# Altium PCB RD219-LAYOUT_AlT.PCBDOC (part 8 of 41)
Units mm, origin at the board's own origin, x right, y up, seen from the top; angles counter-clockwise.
Board outline 209.75 x 159.97 mm, 2 copper layers (TOP, BOTTOM), stack 0 mm thick; 398 components, 199 nets, 1469 pads, 0 vias.
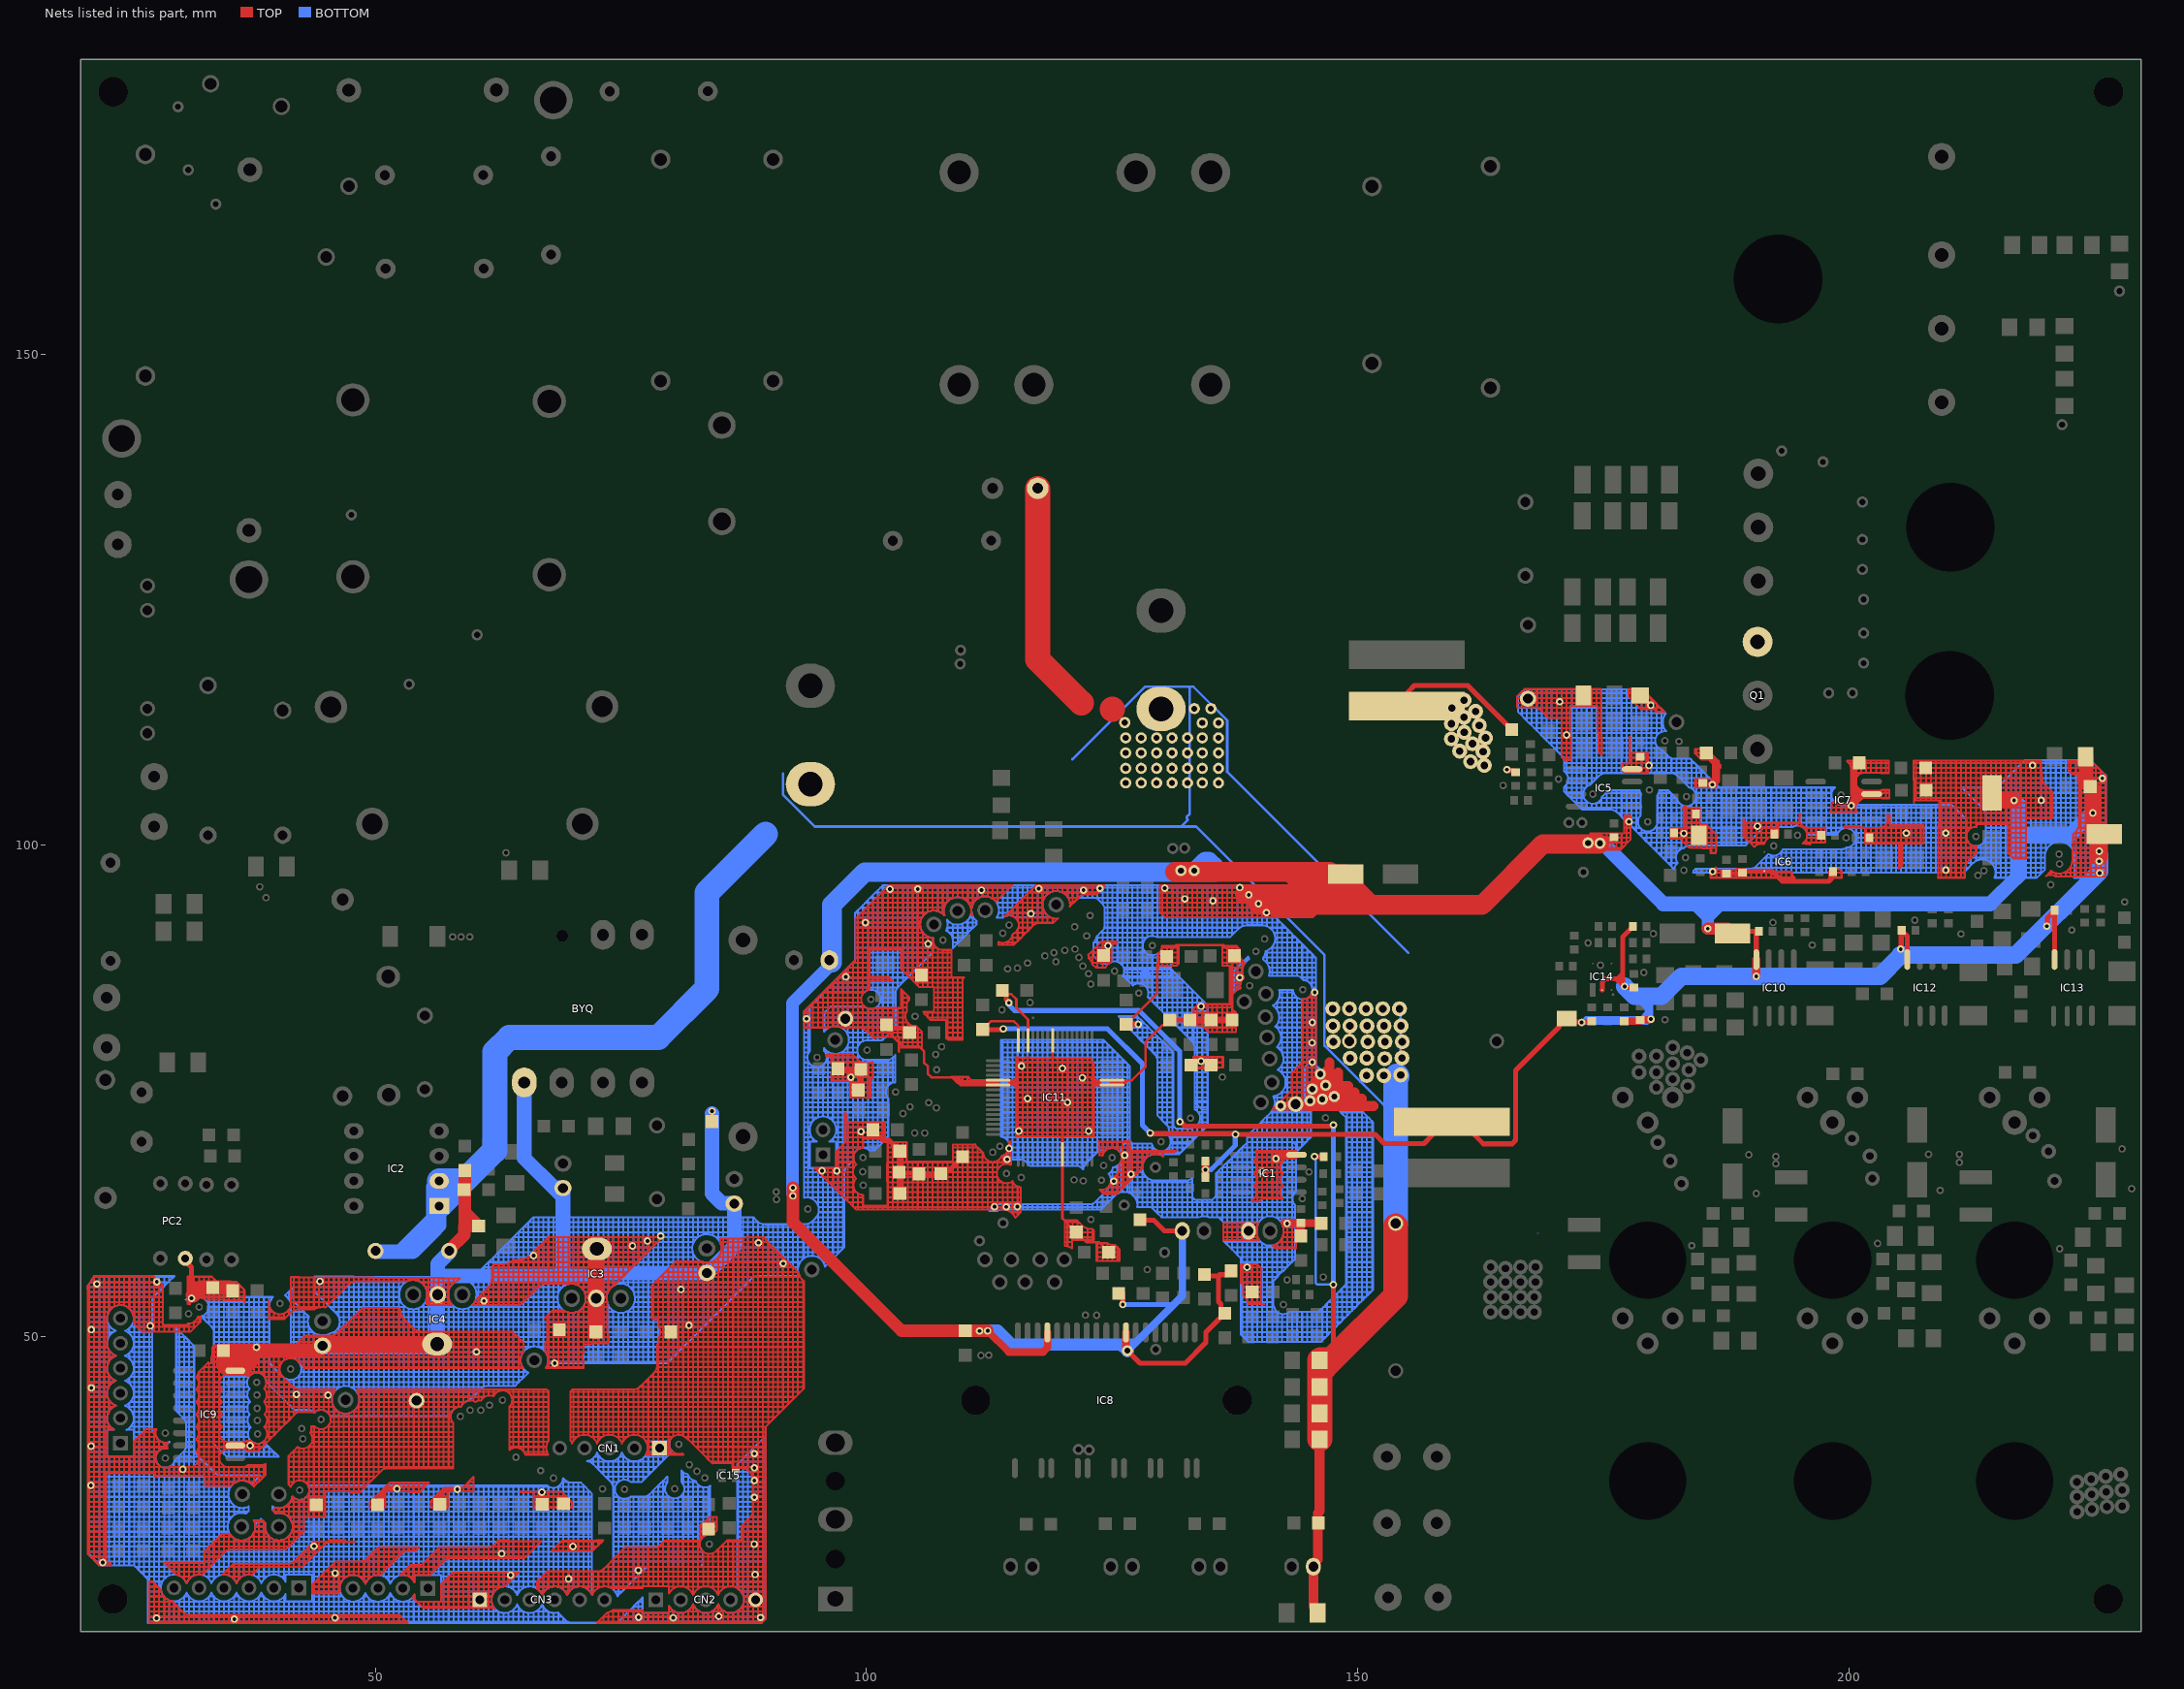
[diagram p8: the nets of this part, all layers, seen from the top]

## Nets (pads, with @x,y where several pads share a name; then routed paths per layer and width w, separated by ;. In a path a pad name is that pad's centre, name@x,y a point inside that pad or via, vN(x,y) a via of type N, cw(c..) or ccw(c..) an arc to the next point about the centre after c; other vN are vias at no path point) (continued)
GND: (continued)
  TOP w0.203: 58.481,28.128 58.481,28.542 ; 58.481,28.128 58.989,28.128 ; 58.481,28.542 58.989,28.542 ; pad.@58.481,34.276 58.989,34.276 ; pad.@58.481,34.276 pad.@58.481,34.638 ; pad.@58.481,34.638 pad.@58.608,34.638 ; 58.481,42.862 58.481,43.368 ; 58.481,43.368 58.989,43.368 ; 58.481,43.368 58.481,43.876 ; 58.481,43.876 58.989,43.876 ; 58.481,43.876 58.481,44.384 ; 58.481,44.384 58.989,44.384 ; 58.481,44.384 58.481,44.635 ; 58.481,44.635 58.989,44.635 ; 58.481,46.838 58.481,46.924 ; 58.481,46.838 58.989,46.838 ; 58.481,46.924 58.481,47.432 ; 58.481,46.924 58.989,46.924 ; 58.481,47.432 58.481,47.94 ; 58.481,47.432 58.989,47.432 ; 58.481,47.94 58.481,48.448 ; 58.481,47.94 58.989,47.94 ; 58.481,48.448 58.481,48.956 ; 58.481,48.448 58.989,48.448 ; 58.481,48.956 58.481,49.464 ; 58.481,48.956 58.989,48.956 ; 58.481,49.464 58.481,49.972 ; 58.481,49.464 58.989,49.464 ; 58.481,49.972 58.481,50.48 ; 58.481,49.972 58.989,49.972 ; 58.481,50.48 58.481,50.525 ; 58.481,50.48 58.989,50.48 ; 58.481,50.525 58.989,50.525 ; 58.481,55.82 58.611,55.95 58.481,55.951 ; 58.481,55.82 58.481,55.951 ; pad.@58.608,34.638 ccw(c58.608,35.367) 58.965,34.732 ; pad.@58.608,34.638 ccw(c58.608,35.367) 58.965,34.732 ; 58.965,34.732 ccw(c58.608,35.367) 58.989,34.746 ; 58.965,34.732 ccw(c58.608,35.367) 58.989,34.746 ; 58.965,34.732 58.989,34.732 ; 58.989,22.372 58.989,22.54 ; 58.989,22.372 59.497,22.372 ; 58.989,22.54 58.989,23.048 ; 58.989,22.54 59.497,22.54 ; 58.989,23.048 58.989,23.556 ; 58.989,23.048 59.497,23.048 ; 58.989,23.556 58.989,24.064 ; 58.989,23.556 59.497,23.556 ; 58.989,24.064 58.989,24.572 ; 58.989,24.064 59.497,24.064 ; 58.989,24.572 58.989,25.08 ; 58.989,24.572 59.497,24.572 ; 58.989,25.08 58.989,25.588 ; 58.989,25.08 59.497,25.08 ; 58.989,25.588 58.989,26.002 ; 58.989,25.588 59.497,25.588 ; 58.989,26.002 59.497,26.002 ; 58.989,27.46 58.989,27.62 ; 58.989,27.46 59.497,27.46 ; 58.989,27.62 58.989,28.128 ; 58.989,27.62 59.497,27.62 ; 58.989,28.128 58.989,28.542 ; 58.989,28.128 59.497,28.128 ; 58.989,28.542 59.497,28.542 ; 58.989,34.276 58.989,34.732 ; 58.989,34.276 59.497,34.276 ; 58.989,34.732 59.497,34.732 ; 58.989,34.732 58.989,34.746 ; 58.989,34.746 ccw(c58.608,35.367) 59.123,34.852 ; 58.989,34.746 ccw(c58.608,35.367) 59.123,34.852 ; 58.989,43.261 cw(c59.646,42.53) 59.133,43.368 ; 58.989,43.261 58.989,43.368 ; 58.989,43.368 58.989,43.876 ; 58.989,43.368 59.133,43.368 ; 58.989,43.876 59.497,43.876 ; 58.989,43.876 58.989,44.384 ; 58.989,44.384 59.497,44.384 ; 58.989,44.384 58.989,44.635 ; 58.989,44.635 59.497,44.635 ; 58.989,46.838 58.989,46.924 ; 58.989,46.838 59.497,46.838 ; 58.989,46.924 58.989,47.432 ; 58.989,46.924 59.497,46.924 ; 58.989,47.432 58.989,47.94 ; 58.989,47.432 59.497,47.432 ; 58.989,47.94 58.989,48.448 ; 58.989,47.94 59.497,47.94 ; 58.989,48.448 58.989,48.956 ; 58.989,48.448 59.497,48.448 ; 58.989,48.956 58.989,49.464 ; 58.989,48.956 59.497,48.956 ; 58.989,49.464 58.989,49.972 ; 58.989,49.464 59.497,49.464 ; 58.989,49.972 58.989,50.48 ; 58.989,49.972 59.497,49.972 ; 58.989,50.48 58.989,50.525 ; 58.989,50.48 59.497,50.48 ; 58.989,50.525 59.497,50.525 ; 59.123,34.852 59.497,35.226 ; 59.133,43.368 cw(c59.646,42.53) 59.492,43.501 cw(c59.646,42.53) 59.497,43.501 ; 59.497,22.372 59.497,22.54 ; 59.497,22.372 60.005,22.372 ; 59.497,22.54 59.497,23.048 ; 59.497,22.54 CN3.1@60.005,22.54 ; 59.497,23.048 59.497,23.556 ; 59.497,23.048 CN3.1@60.005,23.048 ; 59.497,23.556 59.497,24.064 ; 59.497,23.556 CN3.1@60.005,23.556 ; 59.497,24.064 59.497,24.572 ; 59.497,24.064 60.005,24.064 ; 59.497,24.572 59.497,25.08 ; 59.497,24.572 60.005,24.572 ; 59.497,25.08 59.497,25.588 ; 59.497,25.08 60.005,25.08 ; 59.497,25.588 59.497,26.002 ; 59.497,25.588 60.005,25.588 ; 59.497,26.002 60.005,26.002 ; 59.497,27.46 59.497,27.62 ; 59.497,27.46 60.005,27.46 ; 59.497,27.62 59.497,28.128 ; 59.497,27.62 60.005,27.62 ; 59.497,28.128 59.497,28.542 ; 59.497,28.128 60.005,28.128 ; 59.497,28.542 60.005,28.542 ; 59.497,34.276 59.497,34.732 ; 59.497,34.732 60.005,34.732 ; 59.497,34.732 59.497,35.226 ; 59.497,35.226 59.511,35.24 ; 59.497,43.501 59.497,43.876 ; 59.497,43.876 59.497,44.384 ; 59.497,43.876 60.005,43.876 ; 59.497,44.384 59.497,44.635 ; 59.497,44.384 60.005,44.384 ; 59.497,44.635 60.005,44.635 ; 59.497,46.838 59.497,46.924 ; 59.497,46.838 60.005,46.838 ; 59.497,46.924 59.497,47.432 ; 59.497,46.924 60.005,46.924 ; 59.497,47.432 59.497,47.94 ; 59.497,47.432 60.005,47.432 ; 59.497,47.94 59.497,48.448 ; 59.497,47.94 60.005,47.94 ; 59.497,48.448 59.497,48.956 ; 59.497,48.448 pad.@60.005,48.448 ; 59.497,48.956 59.497,49.464 ; 59.497,48.956 60.005,48.956 ; 59.497,49.464 59.497,49.972 ; 59.497,49.464 60.005,49.464 ; 59.497,49.972 59.497,50.48 ; 59.497,49.972 60.005,49.972 ; 59.497,50.48 59.497,50.525 ; 59.497,50.48 60.005,50.48 ; 59.497,50.525 60.005,50.525 ; 59.511,35.24 60.005,35.734 ; 59.511,35.24 60.005,35.24 ; 60.005,22.372 CN3.1@60.005,22.54 ; 60.005,22.372 60.513,22.372 ; CN3.1@60.005,22.54 CN3.1@60.005,23.048 ; CN3.1@60.005,22.54 CN3.1@60.513,22.54 ; CN3.1@60.005,23.048 CN3.1@60.513,23.048 ; CN3.1@60.005,23.048 CN3.1@60.005,23.556 ; CN3.1@60.005,23.556 60.005,24.064 ; CN3.1@60.005,23.556 CN3.1@60.513,23.556 ; 60.005,24.064 60.005,24.572 ; 60.005,24.064 60.513,24.064 ; 60.005,24.572 60.005,25.08 ; 60.005,24.572 60.513,24.572 ; 60.005,25.08 60.005,25.588 ; 60.005,25.08 60.513,25.08 ; 60.005,25.588 60.005,26.002 ; 60.005,25.588 60.513,25.588 ; 60.005,26.002 60.513,26.002 ; 60.005,27.46 60.005,27.62 ; 60.005,27.46 60.513,27.46 ; 60.005,27.62 60.005,28.128 ; 60.005,27.62 60.513,27.62 ; 60.005,28.128 60.005,28.542 ; 60.005,28.128 60.513,28.128 ; 60.005,28.542 60.513,28.542 ; 60.005,34.216 60.005,34.224 ; 60.005,34.216 60.013,34.216 60.013,34.224 ; 60.005,34.224 60.005,34.732 ; 60.005,34.224 60.013,34.224 ; 60.005,34.732 60.005,35.24 ; 60.005,34.732 60.013,34.732 ; 60.005,35.24 60.005,35.734 ; 60.005,35.24 60.013,35.24 ; 60.005,35.734 60.013,35.741 60.013,35.24 ; 60.005,43.876 60.005,44.384 ; 60.005,43.876 60.513,43.876 ; 60.005,44.384 60.005,44.635 ; 60.005,44.384 60.513,44.384 ; 60.005,44.635 60.513,44.635 ; 60.005,46.838 60.005,46.924 ; 60.005,46.838 60.513,46.838 ; 60.005,46.924 60.005,47.432 ; 60.005,46.924 60.513,46.924 ; 60.005,47.432 60.005,47.94 ; 60.005,47.432 60.513,47.432 ; 60.005,47.94 pad.@60.005,48.448 ; 60.005,47.94 60.513,47.94 ; pad.@60.005,48.448 pad.@60.513,48.448 ; pad.@60.005,48.448 60.005,48.956 ; 60.005,48.956 60.005,49.464 ; 60.005,48.956 60.513,48.956 ; 60.005,49.464 60.005,49.972 ; 60.005,49.464 60.513,49.464 ; 60.005,49.972 60.005,50.48 ; 60.005,49.972 60.513,49.972 ; 60.005,50.48 60.005,50.525 ; 60.005,50.48 60.513,50.48 ; 60.005,50.525 60.513,50.525 ; 60.005,53.229 60.513,53.229 ; 60.005,53.229 60.005,53.372 ; 60.005,53.372 ccw(c58.862,54.227) 60.106,53.528 ; 60.013,34.224 60.013,34.732 ; 60.013,34.732 60.013,35.24 ; 60.106,53.528 ccw(c58.862,54.227) 60.192,53.708 ; 60.106,53.528 60.513,53.528 ; 60.192,53.708 60.519,54.036 ; 60.513,22.372 CN3.1@60.513,22.54 ; 60.513,22.372 61.021,22.372 ; CN3.1@60.513,22.54 CN3.1@60.513,23.048 ; CN3.1@60.513,22.54 CN3.1@61.021,22.54 ; CN3.1@60.513,23.048 CN3.1@61.021,23.048 ; CN3.1@60.513,23.048 CN3.1@60.513,23.556 ; CN3.1@60.513,23.556 60.513,24.064 ; CN3.1@60.513,23.556 CN3.1@61.021,23.556 ; 60.513,24.064 60.513,24.572 ; 60.513,24.064 61.021,24.064 ; 60.513,24.572 60.513,25.08 ; 60.513,24.572 61.021,24.572 ; 60.513,25.08 60.513,25.588 ; 60.513,25.08 61.021,25.08 ; 60.513,25.588 60.513,26.002 ; 60.513,25.588 61.021,25.588 ; 60.513,26.002 61.021,26.002 ; 60.513,27.46 60.513,27.62 ; 60.513,27.46 61.021,27.46 ; 60.513,27.62 60.513,28.128 ; 60.513,27.62 61.021,27.62 ; 60.513,28.128 60.513,28.542 ; 60.513,28.128 61.021,28.128 ; 60.513,28.542 61.021,28.542 ; 60.513,43.486 60.513,43.876 ; 60.513,43.876 61.021,43.876 ; 60.513,43.876 60.513,44.384 ; 60.513,44.384 61.021,44.384 ; 60.513,44.384 60.513,44.635 ; 60.513,44.635 61.021,44.635 ; 60.513,46.838 60.513,46.924 ; 60.513,46.838 61.021,46.838 ; 60.513,46.924 60.513,47.432 ; 60.513,46.924 61.021,46.924 ; 60.513,47.432 60.513,47.94 ; 60.513,47.432 61.021,47.432 ; 60.513,47.94 pad.@60.513,48.448 ; 60.513,47.94 61.021,47.94 ; pad.@60.513,48.448 61.021,48.448 ; pad.@60.513,48.448 60.513,48.956 ; 60.513,48.956 60.513,49.464 ; 60.513,48.956 61.021,48.956 ; 60.513,49.464 60.513,49.972 ; 60.513,49.464 61.021,49.464 ; 60.513,49.972 60.513,50.48 ; 60.513,49.972 61.021,49.972 ; 60.513,50.48 60.513,50.525 ; 60.513,50.48 61.021,50.48 ; 60.513,50.525 61.021,50.525 ; 60.513,53.229 61.021,53.229 ; 60.513,53.229 60.513,53.528 ; 60.513,53.528 pad.@61.021,53.528 ; 60.519,54.036 61.027,54.544 ; 60.519,54.036 61.021,54.036 ; 61.021,22.372 CN3.1@61.021,22.54 ; 61.021,22.372 61.529,22.372 ; CN3.1@61.021,22.54 CN3.1@61.021,23.048 ; CN3.1@61.021,22.54 61.529,22.54 ; CN3.1@61.021,23.048 61.529,23.048 ; CN3.1@61.021,23.048 CN3.1@61.021,23.556 ; CN3.1@61.021,23.556 61.021,24.064 ; CN3.1@61.021,23.556 61.529,23.556 ; 61.021,24.064 61.021,24.572 ; 61.021,24.064 61.529,24.064 ; 61.021,24.572 61.021,25.08 ; 61.021,24.572 61.529,24.572 ; 61.021,25.08 61.021,25.588 ; 61.021,25.08 61.529,25.08 ; 61.021,25.588 61.021,26.002 ; 61.021,25.588 61.529,25.588 ; 61.021,26.002 61.529,26.002 ; 61.021,27.46 61.529,27.46 ; 61.021,27.46 61.021,27.62 ; 61.021,27.62 61.529,27.62 ; 61.021,27.62 61.021,28.128 ; 61.021,28.128 61.021,28.542 ; 61.021,28.128 61.529,28.128 ; 61.021,28.542 61.529,28.542 ; 61.021,43.808 cw(c61.632,43.038) 61.118,43.876 ; 61.021,43.808 61.021,43.876 ; 61.021,43.876 61.021,44.384 ; 61.021,43.876 61.118,43.876 ; 61.021,44.384 61.529,44.384 ; 61.021,44.384 61.021,44.635 ; 61.021,44.635 61.529,44.635 ; 61.021,46.838 61.021,46.924 ; 61.021,46.838 61.529,46.838 ; 61.021,46.924 61.021,47.432 ; 61.021,46.924 61.529,46.924 ; 61.021,47.432 61.021,47.94 ; 61.021,47.432 61.529,47.432 ; 61.021,47.94 61.021,48.448 ; 61.021,47.94 61.529,47.94 ; 61.021,48.448 61.021,48.956 ; 61.021,48.448 61.529,48.448 ; 61.021,48.956 61.021,49.464 ; 61.021,48.956 61.529,48.956 ; 61.021,49.464 61.021,49.972 ; 61.021,49.464 61.529,49.464 ; 61.021,49.972 61.021,50.48 ; 61.021,49.972 61.529,49.972 ; 61.021,50.48 61.021,50.525 ; 61.021,50.48 61.529,50.48 ; 61.021,50.525 61.529,50.525 ; 61.021,53.229 pad.@61.021,53.528 ; 61.021,53.229 61.529,53.229 ; pad.@61.021,53.528 61.021,54.036 ; pad.@61.021,53.528 61.529,53.528 ; 61.021,54.036 61.529,54.036 ; 61.027,54.544 61.529,54.544 ; 61.118,43.876 cw(c61.632,43.038) 61.529,44.015 ; 61.529,22.372 62.037,22.372 ; 61.529,22.372 61.529,22.54 ; 61.529,22.54 61.529,23.048 ; 61.529,22.54 62.024,22.54 ; 61.529,23.048 61.529,23.556 ; 61.529,23.048 61.842,23.048 ; 61.529,23.556 61.529,24.064 ; 61.529,23.556 61.866,23.556 ; 61.529,24.064 62.037,24.064 ; 61.529,24.064 61.529,24.572 ; 61.529,24.572 61.529,25.08 ; 61.529,24.572 62.037,24.572 ; 61.529,25.08 61.529,25.588 ; 61.529,25.08 62.037,25.08 ; 61.529,25.588 61.529,26.002 ; 61.529,25.588 62.037,25.588 ; 61.529,26.002 62.037,26.002 ; 61.529,27.46 62.037,27.46 ; 61.529,27.46 61.529,27.62 ; 61.529,27.62 62.037,27.62 ; 61.529,27.62 61.529,28.128 ; 61.529,28.128 62.037,28.128 ; 61.529,28.128 61.529,28.542 ; 61.529,28.542 ccw(c61.529,29.271) 61.886,28.636 ; 61.529,28.542 ccw(c61.529,29.271) 61.886,28.636 ; 61.529,44.015 cw(c61.632,43.038) 62.037,43.933 ; 61.529,44.015 61.529,44.384 ; 61.529,44.384 62.037,44.384 ; 61.529,44.384 61.529,44.635 ; 61.529,44.635 62.037,44.635 ; 61.529,46.838 61.529,46.924 ; 61.529,46.838 62.037,46.838 ; 61.529,46.924 61.529,47.432 ; 61.529,46.924 62.037,46.924 ; 61.529,47.432 61.529,47.94 ; 61.529,47.432 62.037,47.432 ; 61.529,47.94 61.529,48.448 ; 61.529,47.94 62.037,47.94 ; 61.529,48.448 61.529,48.956 ; 61.529,48.448 62.037,48.448 ; 61.529,48.956 61.529,49.464 ; 61.529,48.956 62.037,48.956 ; 61.529,49.464 61.529,49.972 ; 61.529,49.464 62.037,49.464 ; 61.529,49.972 61.529,50.48 ; 61.529,49.972 62.037,49.972 ; 61.529,50.48 61.529,50.525 ; 61.529,50.48 62.037,50.48 ; 61.529,50.525 62.037,50.525 ; 61.529,53.229 61.529,53.528 ; 61.529,53.229 62.037,53.229 ; 61.529,53.528 62.037,53.528 ; 61.529,53.528 61.529,54.036 ; 61.529,54.036 61.529,54.544 ; 61.529,54.036 62.037,54.036 ; 61.529,54.544 62.037,54.544 ; 61.529,54.544 61.529,55.05 ; 61.529,55.05 cw(c60.513,55.941) 61.469,54.985 ccw(c60.513,55.941) 61.529,55.05 ; 61.529,55.05 ccw(c60.513,55.941) 61.531,55.052 ; 61.529,55.05 ccw(c60.513,55.941) 61.531,55.052 ; 61.531,55.052 ccw(c60.513,55.941) 61.81,55.56 ; 61.531,55.052 ccw(c60.513,55.941) 61.81,55.56 ; 61.531,55.052 62.037,55.052 ; 61.81,55.56 ccw(c60.513,55.941) 61.812,55.568 ; 61.81,55.56 ccw(c60.513,55.941) 61.812,55.568 ; 61.81,55.56 62.037,55.56 ; 61.812,55.568 ccw(c60.513,55.941) 61.865,55.941 ; 61.812,55.568 ccw(c60.513,55.941) 61.865,55.941 ; 61.842,23.048 ccw(c63.18,23.241) 62.024,22.54 ; 61.842,23.048 cw(c63.18,23.241) 61.863,23.545 cw(c63.18,23.241) 61.866,23.556 ; 61.865,55.941 61.865,56.068 ; 61.865,56.068 62.037,56.068 ; 61.865,56.068 61.865,56.576 ; 61.865,56.576 62.037,56.576 ; 61.865,56.576 61.865,57.084 ; 61.865,57.084 62.037,57.084 ; 61.865,57.084 61.865,57.159 62.093,57.387 62.545,57.387 ; 61.866,23.556 cw(c63.18,23.241) 62.034,23.957 cw(c63.18,23.241) 62.037,23.962 ; 61.886,28.636 ccw(c61.529,29.271) 62.037,28.749 ; 61.886,28.636 ccw(c61.529,29.271) 62.037,28.749 ; 61.886,28.636 62.037,28.636 ; 62.024,22.54 ccw(c63.18,23.241) 62.037,22.52 ; 62.037,22.372 62.037,22.52 ; 62.037,22.372 62.145,22.372 ; 62.037,22.52 ccw(c63.18,23.241) 62.145,22.372 ; 62.037,23.962 cw(c63.18,23.241) 62.108,24.064 ; 62.037,23.962 62.037,24.064 ; 62.037,24.064 62.037,24.572 ; 62.037,24.064 62.108,24.064 ; 62.037,24.572 62.037,25.08 ; 62.037,24.572 62.545,24.572 ; 62.037,25.08 62.037,25.588 ; 62.037,25.08 62.545,25.08 ; 62.037,25.588 62.037,26.002 ; 62.037,25.588 62.545,25.588 ; 62.037,26.002 62.545,26.002 ; 62.037,27.46 62.545,27.46 ; 62.037,27.46 62.037,27.62 ; 62.037,27.62 62.545,27.62 ; 62.037,27.62 62.037,28.128 ; 62.037,28.128 62.037,28.636 ; 62.037,28.128 pad.@62.545,28.128 ; 62.037,28.636 62.545,28.636 ; 62.037,28.636 62.037,28.749 ; 62.037,28.749 ccw(c61.529,29.271) 62.044,28.756 ; 62.037,28.749 ccw(c61.529,29.271) 62.044,28.756 ; 62.037,43.933 cw(c61.632,43.038) 62.042,43.931 ; 62.037,43.933 62.037,44.384 ; 62.037,44.384 62.037,44.635 ; 62.037,44.384 62.433,44.384 ; 62.037,44.635 62.545,44.635 ; 62.037,46.838 62.037,46.924 ; 62.037,46.838 62.545,46.838 ; 62.037,46.924 62.037,47.432 ; 62.037,46.924 62.545,46.924 ; 62.037,47.432 62.037,47.94 ; 62.037,47.432 62.545,47.432 ; 62.037,47.94 62.037,48.448 ; 62.037,47.94 62.545,47.94 ; 62.037,48.448 62.037,48.956 ; 62.037,48.448 62.545,48.448 ; 62.037,48.956 62.037,49.464 ; 62.037,48.956 62.545,48.956 ; 62.037,49.464 62.037,49.972 ; 62.037,49.464 62.545,49.464 ; 62.037,49.972 62.037,50.48 ; 62.037,49.972 62.545,49.972 ; 62.037,50.48 62.037,50.525 ; 62.037,50.48 62.545,50.48 ; 62.037,50.525 62.545,50.525 ; 62.037,53.229 62.037,53.528 ; 62.037,53.229 62.545,53.229 ; 62.037,53.528 62.037,54.036 ; 62.037,53.528 62.545,53.528 ; 62.037,54.036 62.037,54.544 ; 62.037,54.036 62.545,54.036 ; 62.037,54.544 62.037,55.052 ; 62.037,54.544 62.545,54.544 ; 62.037,55.052 62.037,55.56 ; 62.037,55.052 62.545,55.052 ; 62.037,55.56 62.037,56.068 ; 62.037,55.56 62.545,55.56 ; 62.037,56.068 62.037,56.576 ; 62.037,56.068 62.545,56.068 ; 62.037,56.576 62.545,56.576 ; 62.037,56.576 62.037,57.084 ; 62.037,57.084 62.545,57.084 ; 62.042,43.931 cw(c62.946,43.546) 62.433,44.384 ; 62.044,28.756 62.432,29.144 ; 62.108,24.064 cw(c63.18,23.241) 62.545,24.434 ; 62.432,29.144 62.545,29.257 ; 62.432,29.144 62.545,29.144 ; 62.433,44.384 cw(c62.946,43.546) 62.545,44.443 ; 62.545,24.434 cw(c63.18,23.241) 62.945,24.572 ; 62.545,24.434 62.545,24.572 ; 62.545,24.572 62.545,25.08 ; 62.545,24.572 62.945,24.572 ; 62.545,25.08 62.545,25.588 ; 62.545,25.08 63.053,25.08 ; 62.545,25.588 62.545,26.002 ; 62.545,25.588 63.053,25.588 ; 62.545,26.002 63.053,26.002 ; 62.545,27.46 62.545,27.62 ; 62.545,27.46 63.053,27.46 ; 62.545,27.62 pad.@63.053,27.62 ; 62.545,27.62 pad.@62.545,28.128 ; pad.@62.545,28.128 62.545,28.636 ; pad.@62.545,28.128 pad.@63.053,28.128 ; 62.545,28.636 62.545,29.144 ; 62.545,28.636 63.053,28.636 ; 62.545,29.144 62.545,29.257 ; 62.545,29.144 63.053,29.144 ; 62.545,29.257 62.572,29.283 63.053,29.283 ; 62.545,44.443 cw(c62.946,43.546) 63.049,44.523 cw(c62.946,43.546) 63.053,44.523 ; 62.545,44.443 62.545,44.635 ; 62.545,44.635 63.053,44.635 ; 62.545,46.838 62.545,46.924 ; 62.545,46.838 63.053,46.838 ; 62.545,46.924 62.545,47.432 ; 62.545,46.924 63.053,46.924 ; 62.545,47.432 62.545,47.94 ; 62.545,47.432 63.053,47.432 ; 62.545,47.94 62.545,48.448 ; 62.545,47.94 63.053,47.94 ; 62.545,48.448 62.545,48.956 ; 62.545,48.448 63.053,48.448 ; 62.545,48.956 62.545,49.464 ; 62.545,48.956 63.053,48.956 ; 62.545,49.464 62.545,49.972 ; 62.545,49.464 63.053,49.464 ; 62.545,49.972 62.545,50.48 ; 62.545,49.972 63.053,49.972 ; 62.545,50.48 62.545,50.525 ; 62.545,50.48 63.053,50.48 ; 62.545,50.525 63.053,50.525 ; 62.545,53.229 63.053,53.229 ; 62.545,53.229 62.545,53.528 ; 62.545,53.528 63.053,53.528 ; 62.545,53.528 62.545,54.036 ; 62.545,54.036 62.545,54.544 ; 62.545,54.036 63.053,54.036 ; 62.545,54.544 63.053,54.544 ; 62.545,54.544 62.545,55.052 ; 62.545,55.052 63.053,55.052 ; 62.545,55.052 62.545,55.56 ; 62.545,55.56 62.545,56.068 ; 62.545,55.56 63.053,55.56 ; 62.545,56.068 63.053,56.068 ; 62.545,56.068 62.545,56.576 ; 62.545,56.576 63.053,56.576 ; 62.545,56.576 62.545,57.084 ; 62.545,57.084 63.053,57.084 ; 62.545,57.084 62.545,57.387 ; 62.545,57.387 63.053,57.387 ; 62.945,24.572 cw(c63.18,23.241) 63.053,24.587 ; 63.053,24.587 63.053,25.08 ; 63.053,25.08 63.561,25.08 ; 63.053,25.08 63.053,25.588 ; 63.053,25.588 pad.@63.561,25.588 ; 63.053,25.588 63.053,26.002 ; 63.053,26.002 pad.@63.561,26.002 ; 63.053,27.46 63.561,27.46 ; 63.053,27.46 pad.@63.053,27.62 ; pad.@63.053,27.62 63.561,27.62 ; pad.@63.053,27.62 pad.@63.053,28.128 ; pad.@63.053,28.128 63.053,28.636 ; pad.@63.053,28.128 63.561,28.128 ; 63.053,28.636 63.561,28.636 ; 63.053,28.636 63.053,29.144 ; 63.053,29.144 63.561,29.144 ; 63.053,29.144 63.053,29.283 ; 63.053,29.283 63.561,29.283 ; 63.053,44.523 cw(c62.946,43.546) 63.459,44.384 ; 63.053,44.523 63.053,44.635 ; 63.053,44.635 63.561,44.635 ; 63.053,46.838 63.053,46.924 ; 63.053,46.838 63.561,46.838 ; 63.053,46.924 63.053,47.432 ; 63.053,46.924 63.561,46.924 ; 63.053,47.432 63.053,47.94 ; 63.053,47.432 63.561,47.432 ; 63.053,47.94 63.053,48.448 ; 63.053,47.94 63.561,47.94 ; 63.053,48.448 63.053,48.956 ; 63.053,48.448 63.561,48.448 ; 63.053,48.956 63.053,49.464 ; 63.053,48.956 63.561,48.956 ; 63.053,49.464 63.053,49.972 ; 63.053,49.464 63.561,49.464 ; 63.053,49.972 63.053,50.48 ; 63.053,49.972 63.561,49.972 ; 63.053,50.48 63.053,50.525 ; 63.053,50.48 63.561,50.48 ; 63.053,50.525 63.561,50.525 ; 63.053,53.229 63.053,53.528 ; 63.053,53.229 63.561,53.229 ; 63.053,53.528 63.561,53.528 ; 63.053,53.528 63.053,54.036 ; 63.053,54.036 63.053,54.544 ; 63.053,54.036 63.561,54.036 ; 63.053,54.544 63.561,54.544 ; 63.053,54.544 63.053,55.052 ; 63.053,55.052 63.561,55.052 ; 63.053,55.052 63.053,55.56 ; 63.053,55.56 63.053,56.068 ; 63.053,55.56 63.561,55.56 ; 63.053,56.068 63.561,56.068 ; 63.053,56.068 63.053,56.576 ; 63.053,56.576 63.561,56.576 ; 63.053,56.576 63.053,57.084 ; 63.053,57.084 63.561,57.084 ; 63.053,57.084 63.053,57.387 ; 63.053,57.387 63.057,57.387 ; 63.057,57.387 ccw(c63.057,58.739) 63.561,57.485 ; 63.057,57.387 ccw(c63.057,58.739) 63.561,57.485 ; 63.459,44.384 cw(c62.946,43.546) 63.561,44.312 ; 63.459,44.384 63.561,44.384 ; 63.561,24.967 63.561,25.08 ; 63.561,24.967 63.674,25.08 ; 63.561,25.08 63.674,25.08 ; 63.561,25.08 pad.@63.561,25.588 ; pad.@63.561,25.588 pad.@64.069,25.588 ; pad.@63.561,25.588 pad.@63.561,26.002 ; pad.@63.561,26.002 64.069,26.002 ; 63.561,27.46 63.561,27.62 ; 63.561,27.46 64.069,27.46 ; 63.561,27.62 63.561,28.128 ; 63.561,27.62 64.069,27.62 ; 63.561,28.128 63.561,28.636 ; 63.561,28.128 64.069,28.128 ; 63.561,28.636 63.561,29.144 ; 63.561,28.636 64.069,28.636 ; 63.561,29.144 63.561,29.283 ; 63.561,29.144 64.069,29.144 ; 63.561,44.312 cw(c62.946,43.546) 63.87,43.882 cw(c62.946,43.546) 63.872,43.876 ; 63.561,44.312 63.561,44.384 ; 63.561,44.384 64.069,44.384 ; 63.561,44.384 63.561,44.635 ; 63.561,44.635 64.069,44.635 ; 63.561,46.838 64.069,46.838 ; 63.561,46.838 63.561,46.924 ; 63.561,46.924 64.069,46.924 ; 63.561,46.924 63.561,47.432 ; 63.561,47.432 64.069,47.432 ; 63.561,47.432 63.561,47.94 ; 63.561,47.94 64.069,47.94 ; 63.561,47.94 63.561,48.448 ; 63.561,48.448 64.069,48.448 ; 63.561,48.448 63.561,48.956 ; 63.561,48.956 64.069,48.956 ; 63.561,48.956 63.561,49.464 ; 63.561,49.464 64.069,49.464 ; 63.561,49.464 63.561,49.972 ; 63.561,49.972 64.069,49.972 ; 63.561,49.972 63.561,50.48 ; 63.561,50.48 63.986,50.48 ; 63.561,50.48 63.561,50.525 ; 63.561,50.525 63.941,50.525 63.986,50.48 ; 63.561,53.229 64.069,53.229 ; 63.561,53.229 63.561,53.528 ; 63.561,53.528 64.069,53.528 ; 63.561,53.528 63.561,54.036 ; 63.561,54.036 63.561,54.544 ; 63.561,54.036 64.069,54.036 ; 63.561,54.544 64.069,54.544 ; 63.561,54.544 63.561,55.052 ; 63.561,55.052 64.069,55.052 ; 63.561,55.052 63.561,55.56 ; 63.561,55.56 63.561,56.068 ; 63.561,55.56 64.069,55.56 ; 63.561,56.068 64.069,56.068 ; 63.561,56.068 63.561,56.576 ; 63.561,56.576 64.069,56.576 ; 63.561,56.576 63.561,57.084 ; 63.561,57.084 64.069,57.084 ; 63.561,57.084 63.561,57.485 ; 63.561,57.485 ccw(c63.057,58.739) 63.563,57.486 ; 63.561,57.485 ccw(c63.057,58.739) 63.563,57.486 ; 63.563,57.486 ccw(c63.057,58.739) 63.772,57.592 ; 63.563,57.486 ccw(c63.057,58.739) 63.772,57.592 ; 63.674,25.08 64.069,25.475 ; 63.675,38.483 cw(c64.317,37.739) 64.063,38.688 cw(c64.317,37.739) 64.069,38.69 ; 63.675,38.483 63.675,38.796 ; 63.675,38.796 63.675,39.304 ; 63.675,38.796 64.069,38.796 ; 63.675,39.304 63.675,39.812 ; 63.675,39.304 64.069,39.304 ; 63.675,39.812 64.069,39.812 ; 63.675,39.812 63.675,40.32 ; 63.675,40.32 64.069,40.32 ; 63.675,40.32 63.675,40.828 ; 63.675,40.828 64.069,40.828 ; 63.675,40.828 63.675,41.336 ; 63.675,41.336 64.069,41.336 ; 63.675,41.336 63.675,41.844 ; 63.675,41.844 64.069,41.844 ; 63.675,41.844 63.675,42.352 ; 63.675,42.352 63.675,42.86 ; 63.675,42.352 64.069,42.352 ; 63.675,42.86 64.069,42.86 ; 63.772,57.592 ccw(c63.057,58.739) 63.773,57.593 ; 63.772,57.592 ccw(c63.057,58.739) 63.773,57.593 ; 63.772,57.592 64.069,57.592 ; 63.773,57.593 ccw(c63.057,58.739) 64.013,57.783 cw(c63.057,58.739) 63.773,57.593 ; 63.872,43.876 cw(c62.946,43.546) 63.929,43.546 cw(c62.946,43.546) 63.913,43.368 ; 63.872,43.876 64.069,43.876 ; 63.913,43.368 64.069,43.368 ; 63.986,50.48 64.069,50.397 ; 64.069,25.475 pad.@64.069,25.588 ; 64.069,25.475 64.182,25.588 ; pad.@64.069,25.588 64.182,25.588 ; pad.@64.069,25.588 64.069,26.002 ; 64.069,26.002 64.596,26.002 64.182,25.588 ; 64.069,27.46 64.069,27.62 ; 64.069,27.46 64.577,27.46 ; 64.069,27.62 64.069,28.128 ; 64.069,27.62 64.577,27.62 ; 64.069,28.128 64.069,28.636 ; 64.069,28.128 64.577,28.128 ; 64.069,28.636 64.069,29.144 ; 64.069,28.636 64.577,28.636 ; 64.069,29.144 64.069,29.212 ; 64.069,29.144 64.577,29.144 ; 64.069,29.212 64.577,29.212 ; 64.069,38.69 cw(c64.317,37.739) 64.317,38.722 cw(c64.317,37.739) 64.571,38.688 cw(c64.317,37.739) 64.577,38.687 ; 64.069,38.69 64.069,38.796 ; 64.069,38.796 64.069,39.304 ; 64.069,38.796 64.577,38.796 ; 64.069,39.304 64.069,39.812 ; 64.069,39.304 64.577,39.304 ; 64.069,39.812 64.069,40.32 ; 64.069,39.812 64.577,39.812 ; 64.069,40.32 64.069,40.828 ; 64.069,40.32 64.577,40.32 ; 64.069,40.828 64.069,41.336 ; 64.069,40.828 64.577,40.828 ; 64.069,41.336 64.069,41.844 ; 64.069,41.336 64.577,41.336 ; 64.069,41.844 64.069,42.352 ; 64.069,41.844 64.577,41.844 ; 64.069,42.352 64.069,42.86 ; 64.069,42.352 64.577,42.352 ; 64.069,42.86 64.069,43.368 ; 64.069,42.86 64.577,42.86 ; 64.069,43.368 64.069,43.876 ; 64.069,43.368 64.577,43.368 ; 64.069,43.876 64.069,44.384 ; 64.069,43.876 64.577,43.876 ; 64.069,44.384 64.069,44.635 ; 64.069,44.384 64.577,44.384 ; 64.069,44.635 64.577,44.635 ; 64.069,46.838 64.069,46.924 ; 64.069,46.838 64.577,46.838 ; 64.069,46.924 64.069,47.432 ; 64.069,46.924 64.577,46.924 ; 64.069,47.432 64.069,47.94 ; 64.069,47.432 64.577,47.432 ; 64.069,47.94 64.577,47.94 ; 64.069,47.94 64.069,48.448 ; 64.069,48.448 64.577,48.448 ; 64.069,48.448 64.069,48.956 ; 64.069,48.956 64.577,48.956 ; 64.069,48.956 64.069,49.464 ; 64.069,49.464 64.577,49.464 ; 64.069,49.464 64.069,49.972 ; 64.069,49.972 64.494,49.972 ; 64.069,49.972 64.069,50.397 ; 64.069,50.397 64.494,49.972 ; 64.069,53.229 64.069,53.528 ; 64.069,53.229 64.577,53.229 ; 64.069,53.528 64.069,54.036 ; 64.069,53.528 64.577,53.528 ; 64.069,54.036 64.069,54.544 ; 64.069,54.036 64.577,54.036 ; 64.069,54.544 64.577,54.544 ; 64.069,54.544 64.069,55.052 ; 64.069,55.052 64.577,55.052 ; 64.069,55.052 64.069,55.56 ; 64.069,55.56 64.069,56.068 ; 64.069,55.56 64.577,55.56 ; 64.069,56.068 64.577,56.068 ; 64.069,56.068 64.069,56.576 ; 64.069,56.576 64.577,56.576 ; 64.069,56.576 64.069,57.084 ; 64.069,57.084 64.577,57.084 ; 64.069,57.084 64.069,57.592 ; 64.069,57.592 64.069,57.787 ; 64.069,57.592 64.577,57.592 ; 64.069,57.787 64.577,57.787 ; 64.494,49.972 64.577,49.889 ; 64.577,27.46 65.085,27.46 ; 64.577,27.46 64.577,27.62 ; 64.577,27.62 65.085,27.62 ; 64.577,27.62 64.577,28.128 ; 64.577,28.128 64.577,28.636 ; 64.577,28.128 65.085,28.128 ; 64.577,28.636 65.085,28.636 ; 64.577,28.636 64.577,29.144 ; 64.577,29.144 65.085,29.144 ; 64.577,29.144 64.577,29.212 ; 64.577,29.212 65.085,29.212 ; 64.577,38.687 cw(c64.317,37.739) 65.085,38.352 ; 64.577,38.687 64.577,38.796 ; 64.577,38.796 64.577,39.304 ; 64.577,38.796 65.085,38.796 ; 64.577,39.304 64.577,39.812 ; 64.577,39.304 65.085,39.304 ; 64.577,39.812 64.577,40.32 ; 64.577,39.812 65.085,39.812 ; 64.577,40.32 64.577,40.828 ; 64.577,40.32 65.085,40.32 ; 64.577,40.828 64.577,41.336 ; 64.577,40.828 65.085,40.828 ; 64.577,41.336 64.577,41.844 ; 64.577,41.336 65.085,41.336 ; 64.577,41.844 64.577,42.352 ; 64.577,41.844 65.085,41.844 ; 64.577,42.352 64.577,42.86 ; 64.577,42.352 65.085,42.352 ; 64.577,42.86 64.577,43.368 ; 64.577,42.86 65.085,42.86 ; 64.577,43.368 64.577,43.876 ; 64.577,43.368 65.085,43.368 ; 64.577,43.876 64.577,44.384 ; 64.577,43.876 65.085,43.876 ; 64.577,44.384 64.577,44.635 ; 64.577,44.384 65.085,44.384 ; 64.577,44.635 65.085,44.635 ; 64.577,46.838 64.577,46.924 ; 64.577,46.838 65.02,46.838 ; 64.577,46.924 64.577,47.432 ; 64.577,46.924 64.968,46.924 ; 64.577,47.432 64.577,47.94 ; 64.577,47.432 64.8,47.432 ; 64.577,47.94 64.577,48.448 ; 64.577,47.94 64.828,47.94 ; 64.577,48.448 64.577,48.956 ; 64.577,48.448 65.066,48.448 ; 64.577,48.956 65.085,48.956 ; 64.577,48.956 64.577,49.464 ; 64.577,49.464 64.577,49.889 ; 64.577,53.229 64.577,53.528 ; 64.577,53.528 64.577,54.036 ; 64.577,53.528 65.079,53.528 ; 64.577,54.036 64.577,54.544 ; 64.577,54.036 65.085,54.036 ; 64.577,54.544 65.085,54.544 ; 64.577,54.544 64.577,55.052 ; 64.577,55.052 65.085,55.052 ; 64.577,55.052 64.577,55.56 ; 64.577,55.56 64.577,56.068 ; 64.577,55.56 65.085,55.56 ; 64.577,56.068 65.085,56.068 ; 64.577,56.068 64.577,56.576 ; 64.577,56.576 65.085,56.576 ; 64.577,56.576 64.577,57.084 ; 64.577,57.084 65.085,57.084 ; 64.577,57.084 64.577,57.592 ; 64.577,57.592 64.577,57.787 ; 64.577,57.592 65.085,57.592 ; 64.577,57.787 64.909,57.787 64.909,57.89 ; 64.8,47.432 ccw(c66.19,47.61) 64.968,46.924 ; 64.8,47.432 cw(c66.19,47.61) 64.828,47.94 ; 64.828,47.94 cw(c66.19,47.61) 65.066,48.448 ; 64.909,57.89 cw(c64.827,59.239) 64.827,57.887 ccw(c64.827,59.239) 64.898,57.889 ccw(c64.827,59.239) 64.909,57.89 ; 64.909,57.89 ccw(c64.827,59.239) 65.085,57.912 ; 64.909,57.89 ccw(c64.827,59.239) 65.085,57.912 ; 64.968,46.924 ccw(c66.19,47.61) 65.02,46.838 ; 65.066,48.448 cw(c66.19,47.61) 65.085,48.473 65.085,48.956 ; 65.079,53.528 65.085,53.534 ; 65.085,27.46 65.085,27.62 ; 65.085,27.46 65.164,27.46 65.593,27.888 ; 65.085,27.62 65.085,28.128 ; 65.085,28.128 65.085,28.636 ; 65.085,28.128 65.593,28.128 ; 65.085,28.636 65.085,29.144 ; 65.085,28.636 65.593,28.636 ; 65.085,29.144 65.085,29.212 ; 65.085,29.144 65.593,29.144 ; 65.085,29.212 65.593,29.212 ; 65.085,38.352 cw(c64.317,37.739) 65.132,38.288 ; 65.085,38.352 65.085,38.796 ; 65.085,38.796 65.085,39.304 ; 65.085,38.796 65.593,38.796 ; 65.085,39.304 65.085,39.812 ; 65.085,39.304 65.593,39.304 ; 65.085,39.812 65.085,40.32 ; 65.085,39.812 65.593,39.812 ; 65.085,40.32 65.085,40.828 ; 65.085,40.32 65.593,40.32 ; 65.085,40.828 65.085,41.336 ; 65.085,40.828 65.593,40.828 ; 65.085,41.336 65.085,41.844 ; 65.085,41.336 65.593,41.336 ; 65.085,41.844 65.085,42.352 ; 65.085,41.844 65.593,41.844 ; 65.085,42.352 65.085,42.86 ; 65.085,42.352 65.593,42.352 ; 65.085,42.86 65.085,43.368 ; 65.085,42.86 65.593,42.86 ; 65.085,43.368 65.085,43.876 ; 65.085,43.368 65.593,43.368 ; 65.085,43.876 65.085,44.384 ; 65.085,43.876 65.593,43.876 ; 65.085,44.384 65.085,44.635 ; 65.085,44.384 65.593,44.384 ; 65.085,44.635 65.593,44.635 ; 65.085,48.956 65.091,48.956 ; 65.085,48.956 65.085,49.4 ; 65.084,49.401 cw(c65.898,50.48) 65.029,49.445 ccw(c65.898,50.48) 65.084,49.401 ; 65.085,53.534 65.587,54.036 ; 65.085,53.534 65.085,54.036 ; 65.085,54.036 65.085,54.544 ; 65.085,54.036 65.587,54.036 ; 65.085,54.544 65.085,55.052 ; 65.085,54.544 65.593,54.544 ; 65.085,55.052 65.593,55.052 ; 65.085,55.052 65.085,55.56 ; 65.085,55.56 65.085,56.068 ; 65.085,55.56 65.593,55.56 ; 65.085,56.068 65.593,56.068 ; 65.085,56.068 65.085,56.576 ; 65.085,56.576 65.593,56.576 ; 65.085,56.576 65.085,57.084 ; 65.085,57.084 65.593,57.084 ; 65.085,57.084 65.085,57.592 ; 65.085,57.592 65.593,57.592 ; 65.085,57.592 65.085,57.912 ; 65.085,57.912 ccw(c64.827,59.239) 65.555,58.1 ; 65.085,57.912 ccw(c64.827,59.239) 65.555,58.1 ; 65.132,38.288 65.593,38.288 ; 65.555,58.1 ccw(c64.827,59.239) 65.593,58.125 ; 65.555,58.1 65.593,58.1 ; 65.587,54.036 65.593,54.042 ; 65.593,27.888 65.593,28.128 ; 65.593,27.888 65.833,28.128 ; 65.593,28.128 65.593,28.636 ; 65.593,28.128 65.833,28.128 ; 65.593,28.636 65.593,29.144 ; 65.593,28.636 66.101,28.636 ; 65.593,29.144 65.593,29.212 ; 65.593,29.144 66.101,29.144 ; 65.593,29.212 66.101,29.212 ; 65.593,38.004 65.593,38.288 ; 65.593,38.004 66.101,38.004 ; 65.593,38.288 65.593,38.796 ; 65.593,38.288 66.101,38.288 ; 65.593,38.796 65.593,39.304 ; 65.593,38.796 66.101,38.796 ; 65.593,39.304 65.593,39.812 ; 65.593,39.304 66.101,39.304 ; 65.593,39.812 65.593,40.32 ; 65.593,39.812 66.101,39.812 ; 65.593,40.32 65.593,40.828 ; 65.593,40.32 66.101,40.32 ; 65.593,40.828 65.593,41.336 ; 65.593,40.828 66.101,40.828 ; 65.593,41.336 65.593,41.844 ; 65.593,41.336 66.101,41.336 ; 65.593,41.844 65.593,42.352 ; 65.593,41.844 66.101,41.844 ; 65.593,42.352 65.593,42.86 ; 65.593,42.352 66.101,42.352 ; 65.593,42.86 65.593,43.368 ; 65.593,42.86 66.101,42.86 ; 65.593,43.368 65.593,43.876 ; 65.593,43.368 66.101,43.368 ; 65.593,43.876 65.593,44.384 ; 65.593,43.876 66.101,43.876 ; 65.593,44.384 65.593,44.635 ; 65.593,44.384 66.101,44.384 ; 65.593,44.635 66.101,44.635 ; 65.593,54.042 65.593,54.544 ; 65.593,54.042 66.095,54.544 ; 65.593,54.544 66.095,54.544 ; 65.593,54.544 65.593,55.052 ; 65.593,55.052 66.101,55.052 ; 65.593,55.052 65.593,55.56 ; 65.593,55.56 65.593,56.068 ; 65.593,55.56 66.101,55.56 ; 65.593,56.068 66.101,56.068 ; 65.593,56.068 65.593,56.576 ; 65.593,56.576 66.101,56.576 ; 65.593,56.576 65.593,57.084 ; 65.593,57.084 66.101,57.084 ; 65.593,57.084 65.593,57.592 ; 65.593,57.592 65.593,58.1 ; 65.593,57.592 66.101,57.592 ; 65.593,58.1 pad.@66.101,58.1 ; 65.593,58.1 65.593,58.125 ; 65.593,58.125 ccw(c64.827,59.239) 65.602,58.132 ; 65.833,28.128 66.101,28.396 ; 66.095,54.544 66.101,54.55 ; 66.101,28.396 66.101,28.636 ; 66.101,28.636 66.101,29.144 ; 66.101,29.144 66.101,29.212 ; 66.101,29.144 66.609,29.144 ; 66.101,38.004 66.101,38.288 ; 66.101,38.004 66.609,38.004 ; 66.101,38.288 66.101,38.796 ; 66.101,38.288 66.609,38.288 ; 66.101,38.796 66.101,39.304 ; 66.101,38.796 66.609,38.796 ; 66.101,39.304 66.101,39.812 ; 66.101,39.304 66.609,39.304 ; 66.101,39.812 66.101,40.32 ; 66.101,39.812 66.609,39.812 ; 66.101,40.32 66.101,40.828 ; 66.101,40.32 66.609,40.32 ; 66.101,40.828 66.101,41.336 ; 66.101,40.828 66.609,40.828 ; 66.101,41.336 66.101,41.844 ; 66.101,41.336 66.609,41.336 ; 66.101,41.844 66.101,42.352 ; 66.101,41.844 66.609,41.844 ; 66.101,42.352 66.101,42.86 ; 66.101,42.352 66.609,42.352 ; 66.101,42.86 66.101,43.368 ; 66.101,42.86 66.609,42.86 ; 66.101,43.368 66.101,43.876 ; 66.101,43.368 66.609,43.368 ; 66.101,43.876 66.101,44.384 ; 66.101,43.876 66.609,43.876 ; 66.101,44.384 66.101,44.635 ; 66.101,44.384 66.609,44.384 ; 66.101,44.635 66.609,44.635 ; 66.101,54.55 66.101,55.052 ; 66.101,55.052 66.101,55.56 ; 66.101,55.052 66.607,55.052 ; 66.101,55.56 66.101,56.068 ; 66.101,55.56 66.609,55.56 ; 66.101,56.068 66.609,56.068 ; 66.101,56.068 66.101,56.576 ; 66.101,56.576 66.609,56.576 ; 66.101,56.576 66.101,57.084 ; 66.101,57.084 66.609,57.084 ; 66.101,57.084 66.101,57.592 ; 66.101,57.592 pad.@66.101,58.1 ; 66.101,57.592 66.609,57.592 ; pad.@66.101,58.1 66.609,58.1 ; pad.@66.107,58.608 66.615,59.116 ; pad.@66.107,58.608 66.609,58.608 ; 66.113,32.7 66.113,33.208 ; 66.113,32.7 66.113,32.596 R78.1@66.609,32.596 ; 66.113,32.7 R78.1@66.609,32.7 ; 66.113,33.208 66.113,33.716 ; 66.113,33.208 R78.1@66.609,33.208 ; 66.113,33.716 66.609,33.716 ; 66.449,24.379 cw(c65.72,23.241) 66.609,24.259 ; 66.449,24.379 66.449,24.572 ; 66.449,24.572 66.609,24.572 ; 66.449,24.572 66.449,25.068 66.461,25.08 ; 66.461,25.08 66.609,25.08 ; 66.461,25.08 66.609,25.228 ; 66.607,55.052 ccw(c67.498,54.036) 66.542,54.992 cw(c67.498,54.036) 66.607,55.052 ; 66.607,55.052 cw(c67.498,54.036) 66.609,55.054 ; 66.607,55.052 cw(c67.498,54.036) 66.609,55.054 ; 66.609,24.259 66.609,24.572 ; 66.609,24.572 66.609,25.08 ; 66.609,24.572 67.117,24.572 ; 66.609,25.08 67.117,25.08 ; 66.609,25.08 66.609,25.228 ; 66.609,25.228 66.969,25.588 ; 66.609,28.904 66.849,29.144 ; 66.609,28.904 66.609,29.144 ; 66.609,29.144 66.609,29.213 ; 66.609,29.144 66.849,29.144 ; 66.609,29.213 66.918,29.213 66.849,29.144 ; R78.1@66.609,32.596 R78.1@66.609,32.7 ; R78.1@66.609,32.596 R78.1@67.117,32.596 ; R78.1@66.609,32.7 R78.1@67.117,32.7 ; R78.1@66.609,32.7 R78.1@66.609,33.208 ; R78.1@66.609,33.208 66.609,33.716 ; R78.1@66.609,33.208 R78.1@67.117,33.208 ; 66.609,33.716 67.117,33.716 ; 66.609,33.716 pad.@66.609,34.211 ; pad.@66.609,34.211 pad.@67.117,34.211 ; 66.609,38.004 66.609,38.288 ; 66.609,38.004 67.117,38.004 ; 66.609,38.288 66.609,38.796 ; 66.609,38.288 67.117,38.288 ; 66.609,38.796 66.609,39.304 ; 66.609,38.796 67.117,38.796 ; 66.609,39.304 66.609,39.812 ; 66.609,39.304 67.117,39.304 ; 66.609,39.812 66.609,40.32 ; 66.609,39.812 67.117,39.812 ; 66.609,40.32 66.609,40.828 ; 66.609,40.32 67.117,40.32 ; 66.609,40.828 66.609,41.336 ; 66.609,40.828 67.117,40.828 ; 66.609,41.336 66.609,41.844 ; 66.609,41.336 67.117,41.336 ; 66.609,41.844 66.609,42.352 ; 66.609,41.844 67.117,41.844 ; 66.609,42.352 66.609,42.86 ; 66.609,42.352 67.117,42.352 ; 66.609,42.86 66.609,43.368 ; 66.609,42.86 67.117,42.86 ; 66.609,43.368 66.609,43.876 ; 66.609,43.368 67.117,43.368 ; 66.609,43.876 66.609,44.384 ; 66.609,43.876 67.117,43.876 ; 66.609,44.384 66.609,44.635 ; 66.609,44.384 67.117,44.384 ; 66.609,44.635 67.117,44.635 ; 66.609,55.054 cw(c67.498,54.036) 67.117,55.333 ; 66.609,55.054 cw(c67.498,54.036) 67.117,55.333 ; 66.609,55.054 66.609,55.56 ; 66.609,55.56 66.609,56.068 ; 66.609,55.56 67.117,55.56 ; 66.609,56.068 67.117,56.068 ; 66.609,56.068 66.609,56.576 ; 66.609,56.576 67.117,56.576 ; 66.609,56.576 66.609,57.084 ; 66.609,57.084 67.117,57.084 ; 66.609,57.084 66.609,57.592 ; 66.609,57.592 66.609,58.1 ; 66.609,57.592 67.117,57.592 ; 66.609,58.1 66.609,58.608 ; 66.609,58.1 67.117,58.1 ; 66.609,58.608 67.117,58.608 ; 66.615,59.116 67.123,59.624 ; 66.615,59.116 67.117,59.116 ; 66.969,25.588 67.117,25.588 ; 66.969,25.588 67.117,25.736 ; 67.117,23.962 cw(c68.26,23.241) 67.188,24.064 ; 67.117,23.962 67.117,24.064 ; 67.117,24.064 67.117,24.572 ; 67.117,24.064 67.188,24.064 ; 67.117,24.572 67.625,24.572 ; 67.117,24.572 67.117,25.08 ; 67.117,25.08 67.625,25.08 ; 67.117,25.08 67.117,25.588 ; 67.117,25.588 67.117,25.736 ; 67.117,25.588 67.625,25.588 ; 67.117,25.736 67.477,26.096 ; R78.1@67.117,32.596 R78.1@67.117,32.7 ; R78.1@67.117,32.596 R78.1@67.625,32.596 ; R78.1@67.117,32.7 R78.1@67.625,32.7 ; R78.1@67.117,32.7 R78.1@67.117,33.208 ; R78.1@67.117,33.208 67.117,33.716 ; R78.1@67.117,33.208 R78.1@67.625,33.208 ; 67.117,33.716 67.625,33.716 ; 67.117,33.716 pad.@67.117,34.211 ; pad.@67.117,34.211 67.625,34.211 ; 67.117,38.004 67.117,38.288 ; 67.117,38.288 67.117,38.796 ; 67.117,38.288 67.471,38.288 ; 67.117,38.796 67.117,39.304 ; 67.117,38.796 67.422,38.796 ; 67.117,39.304 67.117,39.812 ; 67.117,39.304 67.575,39.304 ; 67.117,39.812 67.117,40.32 ; 67.117,39.812 67.625,39.812 ; 67.117,40.32 67.117,40.828 ; 67.117,40.32 67.625,40.32 ; 67.117,40.828 67.117,41.336 ; 67.117,40.828 67.625,40.828 ; 67.117,41.336 67.117,41.844 ; 67.117,41.336 67.625,41.336 ; 67.117,41.844 67.117,42.352 ; 67.117,41.844 67.625,41.844 ; 67.117,42.352 67.117,42.86 ; 67.117,42.352 67.625,42.352 ; 67.117,42.86 67.625,42.86 ; 67.117,42.86 67.117,43.368 ; 67.117,43.368 67.117,43.876 ; 67.117,43.368 67.625,43.368 ; 67.117,43.876 67.117,44.384 ; 67.117,43.876 67.625,43.876 ; 67.117,44.384 67.625,44.384 ; 67.117,44.384 67.117,44.635 ; 67.117,44.635 67.467,44.635 67.625,44.477 ; 67.117,55.333 cw(c67.498,54.036) 67.498,55.388 ; 67.117,55.333 cw(c67.498,54.036) 67.498,55.388 ; 67.117,55.333 67.117,55.56 ; 67.117,55.56 67.117,56.068 ; 67.117,55.56 67.625,55.56 ; 67.117,56.068 67.625,56.068 ; 67.117,56.068 67.117,56.576 ; 67.117,56.576 67.625,56.576 ; 67.117,56.576 67.117,57.084 ; 67.117,57.084 67.625,57.084 ; 67.117,57.084 67.117,57.592 ; 67.117,57.592 67.117,58.1 ; 67.117,57.592 67.625,57.592 ; 67.117,58.1 67.117,58.608 ; 67.117,58.1 67.625,58.1 ; 67.117,58.608 67.625,58.608 ; 67.117,58.608 67.117,59.116 ; 67.117,59.116 67.625,59.116 ; 67.123,59.624 67.625,59.624 ; 67.123,59.624 67.631,60.132 68.133,60.132 ; 67.188,24.064 cw(c68.26,23.241) 67.625,24.434 ; 67.294,48.956 67.625,48.956 ; 67.294,48.956 67.294,49.447 67.486,49.447 67.486,49.464 ; 67.314,48.448 cw(c66.19,47.61) 67.55,47.949 cw(c66.19,47.61) 67.552,47.94 ; 67.314,48.448 67.625,48.448 ; 67.323,51.95 67.377,52.004 ; 67.323,51.95 67.486,51.95 67.486,51.496 ; 67.377,52.004 67.625,52.252 ; 67.377,52.004 67.625,52.004 ; 67.412,46.924 ccw(c66.19,47.61) 67.58,47.432 ; 67.412,46.924 67.625,46.924 ; 67.422,38.796 ccw(c68.768,38.669) 67.422,38.787 ccw(c68.768,38.669) 67.471,38.288 ; 67.422,38.796 cw(c68.768,38.669) 67.575,39.304 ; 67.477,26.096 67.625,26.096 ; 67.477,26.096 67.51,26.129 67.625,26.129 ; 67.486,49.464 67.486,49.972 ; 67.486,49.464 67.625,49.464 ; 67.486,49.972 67.486,50.48 ; 67.486,49.972 67.625,49.972 ; 67.486,50.48 67.486,50.988 ; 67.486,50.48 67.625,50.48 ; 67.486,50.988 67.625,50.988 ; 67.486,50.988 67.486,51.496 ; 67.486,51.496 67.625,51.496 ; 67.498,55.388 67.625,55.388 ; 67.552,47.94 cw(c66.19,47.61) 67.592,47.61 cw(c66.19,47.61) 67.58,47.432 ; 67.552,47.94 67.625,47.94 ; 67.575,39.304 cw(c68.768,38.669) 67.625,39.39 ; 67.58,47.432 67.625,47.432 ; 67.625,24.434 cw(c68.26,23.241) 68.025,24.572 ; 67.625,24.434 67.625,24.572 ; 67.625,24.572 67.625,25.08 ; 67.625,24.572 68.025,24.572 ; 67.625,25.08 68.133,25.08 ; 67.625,25.08 67.625,25.588 ; 67.625,25.588 67.625,26.096 ; 67.625,25.588 68.133,25.588 ; 67.625,26.096 68.133,26.096 ; 67.625,26.096 67.625,26.129 ; 67.625,26.129 68.133,26.129 ; R78.1@67.625,32.596 R78.1@67.625,32.7 ; R78.1@67.625,32.596 68.133,32.596 ; R78.1@67.625,32.7 68.133,32.7 ; R78.1@67.625,32.7 R78.1@67.625,33.208 ; R78.1@67.625,33.208 67.625,33.716 ; R78.1@67.625,33.208 68.133,33.208 ; 67.625,33.716 67.625,34.211 ; 67.625,33.716 68.133,33.716 ; 67.625,34.211 68.133,34.211 ; 67.625,39.39 67.625,39.812 ; 67.625,39.812 67.625,40.32 ; 67.625,39.812 67.666,39.812 ; 67.625,40.32 67.625,40.828 ; 67.625,40.32 67.666,40.32 ; 67.625,40.828 67.625,41.336 ; 67.625,40.828 67.666,40.828 ; 67.625,41.336 67.625,41.844 ; 67.625,41.336 67.666,41.336 ; 67.625,41.844 67.625,42.352 ; 67.625,41.844 67.666,41.844 ; 67.625,42.352 67.625,42.86 ; 67.625,42.352 67.666,42.352 ; 67.625,42.86 67.666,42.86 ; 67.625,42.86 67.625,43.368 ; 67.625,43.368 67.625,43.876 ; 67.625,43.368 67.666,43.368 ; 67.625,43.876 67.625,44.384 ; 67.625,43.876 67.666,43.876 ; 67.625,44.384 67.666,44.384 ; 67.625,44.384 67.625,44.477 ; 67.625,44.477 67.666,44.436 67.666,44.384 ; 67.625,46.838 68.133,46.838 ; 67.625,46.838 67.625,46.924 ; 67.625,46.924 68.133,46.924 ; 67.625,46.924 67.625,47.432 ; 67.625,47.432 pad.@68.133,47.432 ; 67.625,47.432 67.625,47.94 ; 67.625,47.94 67.625,48.448 ; 67.625,47.94 68.133,47.94 ; 67.625,48.448 68.133,48.448 ; 67.625,48.448 67.625,48.956 ; 67.625,48.956 67.625,49.464 ; 67.625,48.956 68.133,48.956 ; 67.625,49.464 67.625,49.972 ; 67.625,49.464 68.133,49.464 ; 67.625,49.972 68.133,49.972 ; 67.625,49.972 67.625,50.48 ; 67.625,50.48 C83.2@68.133,50.48 ; 67.625,50.48 67.625,50.988 ; 67.625,50.988 67.625,51.496 ; 67.625,50.988 C83.2@68.133,50.988 ; 67.625,51.496 67.625,52.004 ; 67.625,51.496 68.133,51.496 ; 67.625,52.004 68.133,52.004 ; 67.625,52.004 67.625,52.252 ; 67.625,52.252 67.885,52.512 ; 67.625,55.388 68.133,55.388 ; 67.625,55.388 67.625,55.56 ; 67.625,55.56 67.625,56.068 ; 67.625,55.56 68.133,55.56 ; 67.625,56.068 68.133,56.068 ; 67.625,56.068 67.625,56.576 ; 67.625,56.576 68.133,56.576 ; 67.625,56.576 67.625,57.084 ; 67.625,57.084 68.133,57.084 ; 67.625,57.084 67.625,57.592 ; 67.625,57.592 67.625,58.1 ; 67.625,57.592 68.133,57.592 ; 67.625,58.1 67.625,58.608 ; 67.625,58.1 68.133,58.1 ; 67.625,58.608 67.625,59.116 ; 67.625,58.608 68.133,58.608 ; 67.625,59.116 67.625,59.624 ; 67.625,59.116 68.133,59.116 ; 67.625,59.624 68.133,59.624 ; 67.666,39.812 67.666,40.32 ; 67.666,40.32 67.666,40.828 ; 67.666,40.828 67.666,41.336 ; 67.666,41.336 67.666,41.844 ; 67.666,41.844 67.666,42.352 ; 67.666,42.352 67.666,42.86 ; 67.666,42.86 67.666,43.368 ; 67.666,43.368 67.666,43.876 ; 67.666,43.876 67.666,44.384 ; 67.885,52.512 68.058,52.684 68.133,52.684 ; 67.885,52.512 68.133,52.512 ; 68.025,24.572 cw(c68.26,23.241) 68.133,24.587 ; 68.133,24.587 cw(c68.26,23.241) 68.495,24.572 ; 68.133,24.587 68.133,25.08 ; 68.133,25.08 68.641,25.08 ; 68.133,25.08 68.133,25.588 ; 68.133,25.588 68.133,26.096 ; 68.133,25.588 68.641,25.588 ; 68.133,26.096 68.641,26.096 ; 68.133,26.096 68.133,26.129 ; 68.133,26.129 68.641,26.129 ; 68.133,28.222 68.641,28.222 ; 68.133,28.222 67.987,28.222 68.401,28.636 ; 68.133,32.596 R80.1@68.641,32.596 ; 68.133,32.596 68.133,32.7 ; 68.133,32.7 R80.1@68.641,32.7 ; 68.133,32.7 68.133,33.208 ; 68.133,33.208 R80.1@68.641,33.208 ; 68.133,33.208 68.133,33.716 ; 68.133,33.716 68.641,33.716 ; 68.133,33.716 68.133,34.211 ; 68.133,34.211 68.641,34.211 ; 68.133,46.838 68.133,46.924 ; 68.133,46.838 68.641,46.838 ; 68.133,46.924 68.641,46.924 ; 68.133,46.924 pad.@68.133,47.432 ; pad.@68.133,47.432 68.133,47.94 ; pad.@68.133,47.432 68.641,47.432 ; 68.133,47.94 68.133,48.448 ; 68.133,47.94 68.641,47.94 ; 68.133,48.448 68.641,48.448 ; 68.133,48.448 68.133,48.956 ; 68.133,48.956 68.133,49.464 ; 68.133,48.956 68.641,48.956 ; 68.133,49.464 68.133,49.972 ; 68.133,49.464 68.641,49.464 ; 68.133,49.972 68.641,49.972 ; 68.133,49.972 C83.2@68.133,50.48 ; C83.2@68.133,50.48 C83.2@68.641,50.48 ; C83.2@68.133,50.48 C83.2@68.133,50.988 ; C83.2@68.133,50.988 68.133,51.496 ; C83.2@68.133,50.988 C83.2@68.641,50.988 ; 68.133,51.496 68.133,52.004 ; 68.133,51.496 68.641,51.496 ; 68.133,52.004 68.133,52.512 ; 68.133,52.004 68.641,52.004 ; 68.133,52.512 68.133,52.684 ; 68.133,52.512 68.641,52.512 ; 68.133,52.684 68.641,52.684 ; 68.133,55.388 68.133,55.56 ; 68.133,55.388 68.641,55.388 ; 68.133,55.56 68.133,56.068 ; 68.133,55.56 68.641,55.56 ; 68.133,56.068 68.133,56.576 ; 68.133,56.068 68.641,56.068 ; 68.133,56.576 68.133,57.084 ; 68.133,56.576 68.641,56.576 ; 68.133,57.084 68.133,57.592 ; 68.133,57.084 68.641,57.084 ; 68.133,57.592 68.133,58.1 ; 68.133,57.592 68.641,57.592 ; 68.133,58.1 68.133,58.608 ; 68.133,58.1 68.641,58.1 ; 68.133,58.608 68.133,59.116 ; 68.133,58.608 68.641,58.608 ; 68.133,59.116 68.133,59.624 ; 68.133,59.116 68.641,59.116 ; 68.133,59.624 68.133,60.132 ; 68.133,59.624 68.641,59.624 ; 68.133,60.132 68.641,60.132 ; 68.401,28.636 68.641,28.876 ; 68.401,28.636 68.641,28.636 ; 68.495,24.572 cw(c68.26,23.241) 68.633,24.54 cw(c68.26,23.241) 68.641,24.538 ; 68.495,24.572 68.641,24.572 ; 68.641,24.538 cw(c68.26,23.241) 69.147,24.261 cw(c68.26,23.241) 69.149,24.259 ; 68.641,24.538 68.641,24.572 ; 68.641,24.572 68.641,25.08 ; 68.641,24.572 69.149,24.572 ; 68.641,25.08 68.641,25.588 ; 68.641,25.08 69.149,25.08 ; 68.641,25.588 68.641,26.096 ; 68.641,25.588 69.149,25.588 ; 68.641,26.096 68.641,26.129 ; 68.641,26.096 69.149,26.096 ; 68.641,26.129 69.149,26.129 ; 68.641,28.222 69.149,28.222 ; 68.641,28.222 68.641,28.636 ; 68.641,28.636 69.149,28.636 ; 68.641,28.636 68.641,28.876 ; 68.641,28.876 68.909,29.144 ; R80.1@68.641,32.596 R80.1@68.641,32.7 ; R80.1@68.641,32.596 R80.1@69.149,32.596 ; R80.1@68.641,32.7 R80.1@69.149,32.7 ; R80.1@68.641,32.7 R80.1@68.641,33.208 ; R80.1@68.641,33.208 R80.1@69.149,33.208 ; R80.1@68.641,33.208 68.641,33.716 ; 68.641,33.716 69.149,33.716 ; 68.641,33.716 68.641,34.211 ; 68.641,34.211 69.008,34.211 69.149,34.07 ; 68.641,46.838 69.149,46.838 ; 68.641,46.838 68.641,46.924 ; 68.641,46.924 69.149,46.924 ; 68.641,46.924 68.641,47.432 ; 68.641,47.432 69.149,47.432 ; 68.641,47.432 68.641,47.94 ; 68.641,47.94 68.641,48.448 ; 68.641,47.94 69.149,47.94 ; 68.641,48.448 69.149,48.448 ; 68.641,48.448 68.641,48.956 ; 68.641,48.956 68.641,49.464 ; 68.641,48.956 69.149,48.956 ; 68.641,49.464 68.641,49.972 ; 68.641,49.464 69.149,49.464 ; 68.641,49.972 C83.2@68.641,50.48 ; 68.641,49.972 69.149,49.972 ; C83.2@68.641,50.48 C83.2@69.149,50.48 ; C83.2@68.641,50.48 C83.2@68.641,50.988 ; C83.2@68.641,50.988 68.641,51.496 ; C83.2@68.641,50.988 C83.2@69.149,50.988 ; 68.641,51.496 68.641,52.004 ; 68.641,51.496 69.149,51.496 ; 68.641,52.004 68.641,52.512 ; 68.641,52.004 69.149,52.004 ; 68.641,52.512 68.641,52.684 ; 68.641,52.512 69.149,52.512 ; 68.641,52.684 69.149,52.684 ; 68.641,55.388 68.641,55.56 ; 68.641,55.388 69.149,55.388 ; 68.641,55.56 68.641,56.068 ; 68.641,55.56 69.149,55.56 ; 68.641,56.068 68.641,56.576 ; 68.641,56.068 69.149,56.068 ; 68.641,56.576 68.641,57.084 ; 68.641,56.576 69.149,56.576 ; 68.641,57.084 68.641,57.592 ; 68.641,57.084 69.149,57.084 ; 68.641,57.592 68.641,58.1 ; 68.641,57.592 69.149,57.592 ; 68.641,58.1 68.641,58.608 ; 68.641,58.1 69.149,58.1 ; 68.641,58.608 68.641,59.116 ; 68.641,58.608 69.149,58.608 ; 68.641,59.116 68.641,59.624 ; 68.641,59.116 69.149,59.116 ; 68.641,59.624 68.641,60.132 ; 68.641,59.624 69.149,59.624 ; 68.641,60.132 69.149,60.132 ; 68.909,29.144 69.149,29.144 ; 68.909,29.144 69.01,29.244 69.149,29.244 ; 69.149,24.259 69.149,24.572 ; 69.149,24.572 69.149,25.08 ; 69.149,24.572 69.657,24.572 ; 69.149,25.08 69.149,25.588 ; 69.149,25.08 pad.@69.657,25.08 ; 69.149,25.588 69.149,26.096 ; 69.149,25.588 pad.@69.657,25.588 ; 69.149,26.096 69.149,26.129 ; 69.149,26.096 69.657,26.096 ; 69.149,26.129 69.657,26.129 ; 69.149,28.222 69.149,28.636 ; 69.149,28.222 69.657,28.222 ; 69.149,28.636 69.149,29.144 ; 69.149,28.636 69.657,28.636 ; 69.149,29.144 69.149,29.244 ; 69.149,29.144 69.657,29.144 ; 69.149,29.244 69.657,29.244 ; R80.1@69.149,32.596 R80.1@69.149,32.7 ; R80.1@69.149,32.596 R80.1@69.657,32.596 ; R80.1@69.149,32.7 R80.1@69.657,32.7 ; R80.1@69.149,32.7 R80.1@69.149,33.208 ; R80.1@69.149,33.208 69.149,33.716 ; R80.1@69.149,33.208 R80.1@69.657,33.208 ; 69.149,33.716 69.149,34.07 ; 69.149,33.716 69.503,33.716 ; 69.149,34.07 69.503,33.716 ; 69.149,46.838 69.149,46.924 ; 69.149,46.838 69.657,46.838 ; 69.149,46.924 69.657,46.924 ; 69.149,46.924 69.149,47.432 ; 69.149,47.432 69.657,47.432 ; 69.149,47.432 69.149,47.94 ; 69.149,47.94 69.149,48.448 ; 69.149,47.94 69.657,47.94 ; 69.149,48.448 69.657,48.448 ; 69.149,48.448 69.149,48.956 ; 69.149,48.956 69.149,49.464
